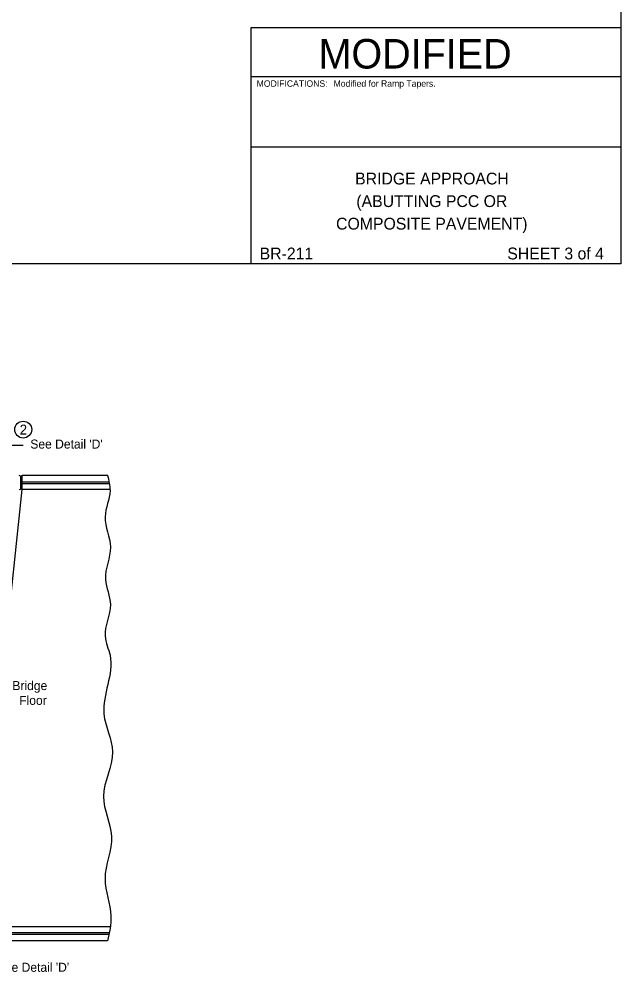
# Model space of a CAD drawing. Extents: x 10045 to 81668, y 6370 to 11018.
# Drawn here: x 19347 to 20468, y 6606 to 8380 of the extents above; entities that cross this region are included whole.
import ezdxf

# ---------------------------------------------------------------- set-up
doc = ezdxf.new("R2010")
doc.units = 0
for name, color, linetype in [('Alignment', 7, 'Continuous'), ('Bridge', 7, 'Continuous'), ('dsnStdLineWork', 7, 'Continuous'), ('Level 5', 7, 'Continuous')]:
    doc.layers.add(name, color=color, linetype=linetype)

msp = doc.modelspace()

# ---------------------------------------------------------------- linework, layer by layer
at = {"layer": 'Alignment'}
msp.add_line((19321.9, 7586.8), (19354.9, 7586.8), dxfattribs=at)
at = {"layer": 'Bridge'}
for p, q in [((19779.5, 8272.7), (20467.5, 8272.7)), ((19779.5, 8142.2), (20467.5, 8142.2))]:
    msp.add_line(p, q, dxfattribs=at)
msp.add_lwpolyline([(19779.5, 8364), (20467.5, 8364), (20467.5, 7924), (19779.5, 7924)], close=True, dxfattribs=at)
at = {"layer": 'dsnStdLineWork'}
for p, q in [((19350, 7528.8), (19347.2, 7529.9)), ((19350, 7528.8), (19352.8, 7529.9)), ((19350, 7528.8), (19350, 7504.9)), ((19512.2, 7529.9), (19352.8, 7529.9)), ((19352.8, 7503.7), (19352.8, 7529.9)), ((19347.2, 7503.7), (19350, 7504.9)), ((19352.8, 7503.7), (19350, 7504.9)), ((19515.2, 7517.6), (19352.8, 7517.6)), ((19515.7, 7514.5), (19352.8, 7514.5)), ((19267.2, 6689.6), (19352.8, 7503.7)), ((19516.5, 7503.7), (19352.8, 7503.7)), ((19517.1, 6689.6), (19267.2, 6689.6)), ((19515.4, 6678.8), (19267.2, 6678.8)), ((19515, 6675.7), (19267.2, 6675.7)), ((19511.9, 6663.4), (19267.2, 6663.4))]:
    msp.add_line(p, q, dxfattribs=at)
msp.add_circle((19355, 7615.5), 15.7, dxfattribs=at)
msp.add_spline([(19512.1, 7529.9), (19516.5, 7502.2), (19507.4, 7453.1), (19517.2, 7396.9), (19508, 7336.7), (19517.2, 7289.6), (19507.4, 7230.8), (19516.5, 7195.5), (19505.2, 7086.2), (19521.2, 7015.3), (19504.2, 6932.5), (19519.2, 6858.6), (19507.2, 6778.8), (19518.2, 6709.9), (19512, 6663.4)], degree=3, dxfattribs=at)
at = {"layer": 'Level 5'}
msp.add_lwpolyline([(17332.5, 9944), (20467.5, 9944), (20467.5, 7924), (17332.5, 7924)], close=True, dxfattribs=at)

# ---------------------------------------------------------------- texts
at = {"layer": 'Alignment'}
for s, height, p in [('2', 18.4, (19348.4, 7606.3)), ("See Detail 'D'", 16.8, (19368.2, 7580.2)), ('Bridge', 16.8, (19334.8, 7130.5)), ('Floor', 16.8, (19347.5, 7103)), ("See Detail 'D'", 16.8, (19305.8, 6606))]:
    msp.add_text(s, height=height, dxfattribs=at).set_placement(p)
at = {"layer": 'Bridge'}
for s, height, p in [('MODIFIED', 55, (19904.6, 8287.8)), ('MODIFICATIONS:', 12, (19789.5, 8253.8)), ('Modified for Ramp Tapers.', 12, (19932.7, 8253.8)), ('BRIDGE APPROACH', 22, (19972.7, 8071.9)), ('(ABUTTING PCC OR', 22, (19975, 8029.9)), ('COMPOSITE PAVEMENT)', 22, (19937.3, 7987.9)), ('BR-211', 22, (19795, 7932.4)), ('SHEET 3 of 4', 22, (20256, 7932.4))]:
    msp.add_text(s, height=height, dxfattribs=at).set_placement(p)

doc.saveas('drawing.dxf')
